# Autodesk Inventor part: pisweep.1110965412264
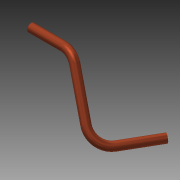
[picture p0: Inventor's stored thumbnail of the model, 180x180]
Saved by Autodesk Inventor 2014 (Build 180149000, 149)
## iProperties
TPVersion: 11.0.2
Company: Autodesk, Inc.
Created: 2005-03
Material: Copper
Description: Tube
Document SubType Name: Modeling
Designer: Autodesk, Inc.
Stock Number: ASTM B 88 Tube 3/4 - Type L
Categories: <pipe>
Density: 1 g/cm^3
Appearance: Copper - Satin
PL: 17.348 in
OD: 0.438 in
ID: 0.393 in
Author: Autodesk, Inc.
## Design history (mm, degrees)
sketch "3D Sketch2" dims "d3" = 50.7999, "d4" = 50.7999
workpoint "Work Point6"
workpoint "Work Point7"
workpoint "Work Point8"
workpoint "Work Point9"
workplane "Work Plane2"
sketch "Sketch2"
  geometry: C1 r 11.113 at (0, 0); C2 r 9.97 at (0, 0); 1 further point
  constraints: 2 centre point
workpoint "Work Point10"
sweep "Sweep2" dims "d5" = 0
body "Solid1"
other parameters: "PL" = 440.6392 [user parameter], "OD" = 11.1125 [user parameter], "ID" = 9.9695 [user parameter]
